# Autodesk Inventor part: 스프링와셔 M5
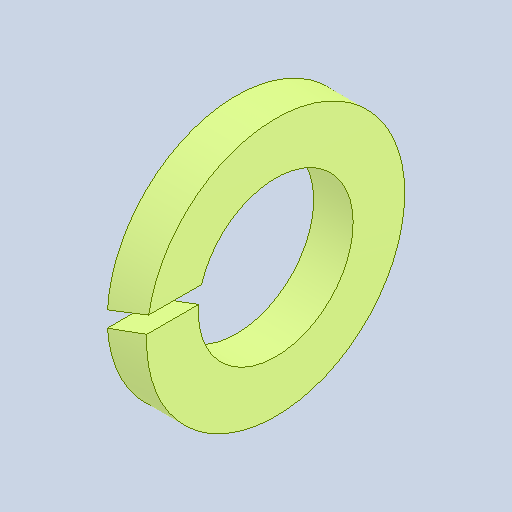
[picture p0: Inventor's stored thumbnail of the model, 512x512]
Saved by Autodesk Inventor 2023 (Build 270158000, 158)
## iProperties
Created: 2024-09
Part Number: 스프링와셔 M5
Material: 강철, 연강
Description: 스프링 잠금 와셔
Document SubType Name: Modeling
Designer: home
Density: 7.85 g/cm^3
Appearance: 기본값
Author: jhkim
Sending System: Autodesk Inventor 2025
Preprocessor: ST-DEVELOPER v20
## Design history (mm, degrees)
feature "Solid1"
node "솔리드1"
